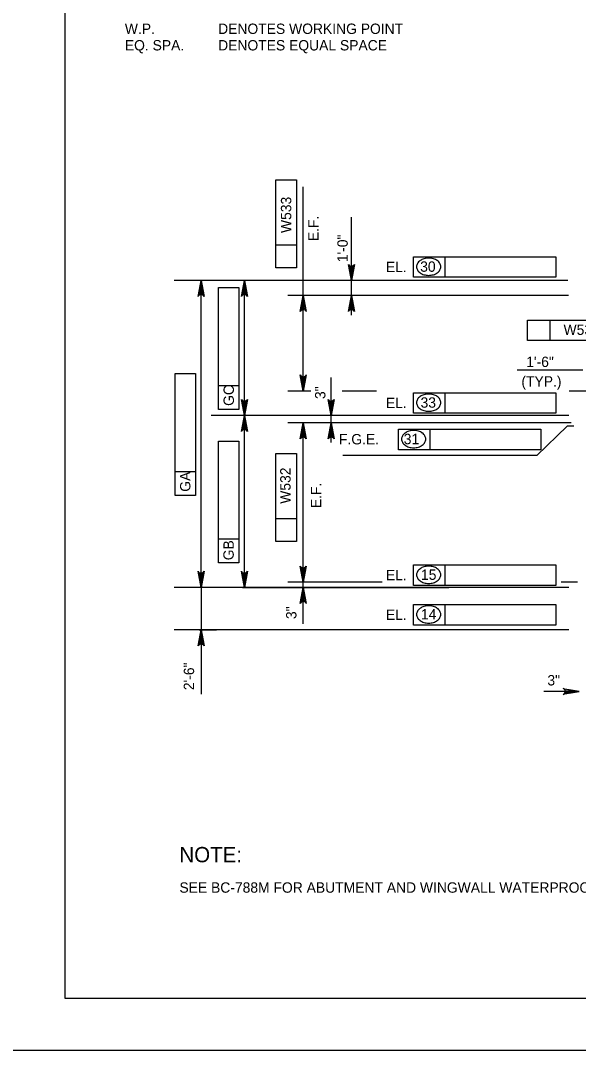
# Model space of a CAD drawing. Extents: x 638340 to 640242, y 295465 to 298435.
# Drawn here: x 639303.6 to 639464.9, y 297841.5 to 298139.3 of the extents above; entities that cross this region are included whole.
import ezdxf

# ---------------------------------------------------------------- set-up
doc = ezdxf.new("R2010")
doc.units = 0
for name, color, linetype in [('2', 7, 'Continuous'), ('4', 7, 'Continuous'), ('Level 3', 7, 'Continuous'), ('Level 4', 7, 'Continuous'), ('PLT-BNDY', 7, 'Continuous')]:
    doc.layers.add(name, color=color, linetype=linetype)

msp = doc.modelspace()

# ---------------------------------------------------------------- linework, layer by layer
at = {"layer": '2'}
for p, q in [((639316.46, 297856.46), (639316.46, 298420.46)), ((640102.46, 297856.46), (639316.46, 297856.46))]:
    msp.add_line(p, q, dxfattribs=at)
at = {"layer": 'Level 3'}
for p, q in [((639466.19, 298038.15), (639447.21, 298038.15)), ((639463.59, 298022.02), (639461.64, 298022.02))]:
    msp.add_line(p, q, dxfattribs=at)
at = {"layer": 'Level 4'}
for p, q in [((639377.42, 298067.77), (639377.42, 298093.26)), ((639377.42, 298093.26), (639383.32, 298093.26)), ((639383.32, 298093.26), (639383.32, 298067.77)), ((639385.3, 298035.1), (639385.3, 298091.24)), ((639399.23, 298054.11), (639399.23, 298082.41)), ((639383.32, 298074.35), (639377.42, 298074.35)), ((639417.21, 298070.94), (639458.34, 298070.94)), ((639417.21, 298065.04), (639417.21, 298070.94)), ((639426.36, 298065.04), (639426.36, 298070.94)), ((639458.34, 298070.94), (639458.34, 298065.04)), ((639383.32, 298067.77), (639377.42, 298067.77)), ((639461.86, 298064.14), (639347.97, 298064.14)), ((639363.31, 298064.14), (639351.37, 298064.14)), ((639380.68, 298064.14), (639363.89, 298064.14)), ((639427.63, 298064.14), (639391.86, 298064.14)), ((639458.34, 298065.04), (639417.21, 298065.04)), ((639355.79, 297978.3), (639355.79, 298061.19)), ((639360.79, 298026.83), (639360.79, 298062.07)), ((639360.79, 298062.07), (639366.69, 298062.07)), ((639366.69, 298062.07), (639366.69, 298026.83)), ((639368.31, 298028.04), (639368.31, 298061.19)), ((639461.97, 298059.78), (639380.88, 298059.78)), ((639450.16, 298052.66), (639475.65, 298052.66)), ((639450.16, 298046.76), (639450.16, 298052.66)), ((639456.74, 298046.76), (639456.74, 298052.66)), ((639475.65, 298046.76), (639450.16, 298046.76)), ((639348.27, 298001.97), (639348.27, 298037.2)), ((639348.27, 298037.2), (639354.16, 298037.2)), ((639354.16, 298037.2), (639354.16, 298001.97)), ((639393.36, 298017.27), (639393.36, 298036.04)), ((639366.69, 298033.67), (639360.79, 298033.67)), ((639387.51, 298032.15), (639380.88, 298032.15)), ((639406.53, 298032.15), (639396.53, 298032.15)), ((639417.21, 298031.63), (639458.34, 298031.63)), ((639417.21, 298025.74), (639417.21, 298031.63)), ((639426.36, 298025.74), (639426.36, 298031.63)), ((639458.34, 298031.63), (639458.34, 298025.74)), ((639478.24, 298032.15), (639462.24, 298032.15)), ((639462.14, 298025.09), (639358.72, 298025.09)), ((639366.69, 298026.83), (639360.79, 298026.83)), ((639434.02, 298025.09), (639363.89, 298025.09)), ((639427.63, 298025.09), (639363.89, 298025.09)), ((639458.34, 298025.74), (639417.21, 298025.74)), ((639368.31, 297978.3), (639368.31, 298022.14)), ((639462.75, 298022.94), (639380.88, 298022.94)), ((639461.64, 298022.02), (639452.82, 298013.52)), ((639385.3, 297975.36), (639385.3, 298019.99)), ((639412.87, 298021.08), (639454, 298021.08)), ((639412.87, 298015.19), (639412.87, 298021.08)), ((639422.03, 298015.19), (639422.03, 298021.08)), ((639454, 298021.08), (639454, 298015.19)), ((639360.79, 297982.44), (639360.79, 298017.68)), ((639360.79, 298017.68), (639366.69, 298017.68)), ((639366.69, 298017.68), (639366.69, 297982.44)), ((639454, 298015.19), (639412.87, 298015.19)), ((639377.42, 297988.6), (639377.42, 298014.09)), ((639377.42, 298014.09), (639383.32, 298014.09)), ((639383.32, 298014.09), (639383.32, 297988.6)), ((639452.82, 298013.52), (639396.79, 298013.52)), ((639354.16, 298008.8), (639348.27, 298008.8)), ((639354.16, 298001.97), (639348.27, 298001.97)), ((639383.32, 297995.18), (639377.42, 297995.18)), ((639366.69, 297989.28), (639360.79, 297989.28)), ((639383.32, 297988.6), (639377.42, 297988.6)), ((639366.69, 297982.44), (639360.79, 297982.44)), ((639417.21, 297981.84), (639458.34, 297981.84)), ((639417.21, 297975.94), (639417.21, 297981.84)), ((639426.36, 297975.94), (639426.36, 297981.84)), ((639458.34, 297981.84), (639458.34, 297975.94)), ((639408.14, 297976.89), (639380.88, 297976.89)), ((639464.62, 297976.89), (639459.85, 297976.89)), ((639462.14, 297975.36), (639347.97, 297975.36)), ((639363.31, 297975.36), (639351.37, 297975.36)), ((639355.79, 297975.36), (639355.79, 297963.08)), ((639434.02, 297975.36), (639363.89, 297975.36)), ((639367.71, 297975.36), (639427.45, 297975.36)), ((639458.34, 297975.94), (639417.21, 297975.94)), ((639385.3, 297964.81), (639385.3, 297972.41)), ((639417.21, 297970.37), (639458.34, 297970.37)), ((639417.21, 297964.48), (639417.21, 297970.37)), ((639426.36, 297964.48), (639426.36, 297970.37)), ((639458.34, 297970.37), (639458.34, 297964.48)), ((639388.75, 297963.08), (639347.97, 297963.08)), ((639355.19, 297963.08), (639360.21, 297963.08)), ((639462.14, 297963.08), (639388.75, 297963.08)), ((639458.34, 297964.48), (639417.21, 297964.48)), ((639355.79, 297960.13), (639355.79, 297944.5)), ((639459.23, 297945.27), (639454.86, 297945.27)), ((639462.18, 297945.27), (639459.23, 297945.27))]:
    msp.add_line(p, q, dxfattribs=at)
for points in [[(639399.23, 298064.14), (639398.36, 298068.79), (639398.61, 298068.43), (639398.92, 298068.25), (639399.23, 298068.19), (639399.55, 298068.25), (639399.86, 298068.43), (639400.1, 298068.79), (639399.23, 298064.14), (639399.86, 298068.43), (639399.55, 298068.25), (639399.23, 298064.14), (639399.23, 298068.19), (639398.92, 298068.25), (639399.23, 298064.14), (639398.61, 298068.43)], [(639355.79, 298064.14), (639356.66, 298059.49), (639356.41, 298059.84), (639356.1, 298060.03), (639355.79, 298060.08), (639355.48, 298060.03), (639355.16, 298059.84), (639354.92, 298059.49), (639355.79, 298064.14), (639355.16, 298059.84), (639355.48, 298060.03), (639355.79, 298064.14), (639355.79, 298060.08), (639356.1, 298060.03), (639355.79, 298064.14), (639356.41, 298059.84)], [(639368.31, 298064.14), (639369.18, 298059.49), (639368.93, 298059.84), (639368.62, 298060.03), (639368.31, 298060.08), (639368, 298060.03), (639367.69, 298059.84), (639367.44, 298059.49), (639368.31, 298064.14), (639367.69, 298059.84), (639368, 298060.03), (639368.31, 298064.14), (639368.31, 298060.08), (639368.62, 298060.03), (639368.31, 298064.14), (639368.93, 298059.84)], [(639385.3, 298059.78), (639386.17, 298055.13), (639385.92, 298055.49), (639385.61, 298055.67), (639385.3, 298055.72), (639384.99, 298055.67), (639384.67, 298055.49), (639384.43, 298055.13), (639385.3, 298059.78), (639384.67, 298055.49), (639384.99, 298055.67), (639385.3, 298059.78), (639385.3, 298055.72), (639385.61, 298055.67), (639385.3, 298059.78), (639385.92, 298055.49)], [(639399.23, 298059.78), (639400.1, 298055.13), (639399.86, 298055.49), (639399.55, 298055.67), (639399.23, 298055.72), (639398.92, 298055.67), (639398.61, 298055.49), (639398.36, 298055.13), (639399.23, 298059.78), (639398.61, 298055.49), (639398.92, 298055.67), (639399.23, 298059.78), (639399.23, 298055.72), (639399.55, 298055.67), (639399.23, 298059.78), (639399.86, 298055.49)], [(639385.3, 298032.15), (639384.43, 298036.8), (639384.67, 298036.44), (639384.99, 298036.26), (639385.3, 298036.2), (639385.61, 298036.26), (639385.92, 298036.44), (639386.17, 298036.8), (639385.3, 298032.15), (639385.92, 298036.44), (639385.61, 298036.26), (639385.3, 298032.15), (639385.3, 298036.2), (639384.99, 298036.26), (639385.3, 298032.15), (639384.67, 298036.44)], [(639368.31, 298025.09), (639367.44, 298029.74), (639367.69, 298029.38), (639368, 298029.2), (639368.31, 298029.14), (639368.62, 298029.2), (639368.93, 298029.38), (639369.18, 298029.74), (639368.31, 298025.09), (639368.93, 298029.38), (639368.62, 298029.2), (639368.31, 298025.09), (639368.31, 298029.14), (639368, 298029.2), (639368.31, 298025.09), (639367.69, 298029.38)], [(639393.36, 298025.09), (639392.48, 298029.74), (639392.73, 298029.38), (639393.04, 298029.2), (639393.36, 298029.14), (639393.67, 298029.2), (639393.98, 298029.38), (639394.23, 298029.74), (639393.36, 298025.09), (639393.98, 298029.38), (639393.67, 298029.2), (639393.36, 298025.09), (639393.36, 298029.14), (639393.04, 298029.2), (639393.36, 298025.09), (639392.73, 298029.38)], [(639368.31, 298025.09), (639369.18, 298020.44), (639368.93, 298020.8), (639368.62, 298020.98), (639368.31, 298021.03), (639368, 298020.98), (639367.69, 298020.8), (639367.44, 298020.44), (639368.31, 298025.09), (639367.69, 298020.8), (639368, 298020.98), (639368.31, 298025.09), (639368.31, 298021.03), (639368.62, 298020.98), (639368.31, 298025.09), (639368.93, 298020.8)], [(639385.3, 298022.94), (639386.17, 298018.29), (639385.92, 298018.65), (639385.61, 298018.83), (639385.3, 298018.88), (639384.99, 298018.83), (639384.67, 298018.65), (639384.43, 298018.29), (639385.3, 298022.94), (639384.67, 298018.65), (639384.99, 298018.83), (639385.3, 298022.94), (639385.3, 298018.88), (639385.61, 298018.83), (639385.3, 298022.94), (639385.92, 298018.65)], [(639393.36, 298022.94), (639394.23, 298018.29), (639393.98, 298018.65), (639393.67, 298018.83), (639393.36, 298018.88), (639393.04, 298018.83), (639392.73, 298018.65), (639392.48, 298018.29), (639393.36, 298022.94), (639392.73, 298018.65), (639393.04, 298018.83), (639393.36, 298022.94), (639393.36, 298018.88), (639393.67, 298018.83), (639393.36, 298022.94), (639393.98, 298018.65)], [(639355.79, 297975.36), (639354.92, 297980.01), (639355.16, 297979.65), (639355.48, 297979.46), (639355.79, 297979.41), (639356.1, 297979.46), (639356.41, 297979.65), (639356.66, 297980.01), (639355.79, 297975.36), (639356.41, 297979.65), (639356.1, 297979.46), (639355.79, 297975.36), (639355.79, 297979.41), (639355.48, 297979.46), (639355.79, 297975.36), (639355.16, 297979.65)], [(639368.31, 297975.36), (639367.44, 297980.01), (639367.69, 297979.65), (639368, 297979.46), (639368.31, 297979.41), (639368.62, 297979.46), (639368.93, 297979.65), (639369.18, 297980.01), (639368.31, 297975.36), (639368.93, 297979.65), (639368.62, 297979.46), (639368.31, 297975.36), (639368.31, 297979.41), (639368, 297979.46), (639368.31, 297975.36), (639367.69, 297979.65)], [(639385.3, 297976.89), (639384.43, 297981.54), (639384.67, 297981.19), (639384.99, 297981), (639385.3, 297980.95), (639385.61, 297981), (639385.92, 297981.19), (639386.17, 297981.54), (639385.3, 297976.89), (639385.92, 297981.19), (639385.61, 297981), (639385.3, 297976.89), (639385.3, 297980.95), (639384.99, 297981), (639385.3, 297976.89), (639384.67, 297981.19)], [(639385.3, 297975.36), (639386.17, 297970.7), (639385.92, 297971.06), (639385.61, 297971.25), (639385.3, 297971.3), (639384.99, 297971.25), (639384.67, 297971.06), (639384.43, 297970.7), (639385.3, 297975.36), (639384.67, 297971.06), (639384.99, 297971.25), (639385.3, 297975.36), (639385.3, 297971.3), (639385.61, 297971.25), (639385.3, 297975.36), (639385.92, 297971.06)], [(639355.79, 297963.08), (639356.66, 297958.43), (639356.41, 297958.78), (639356.1, 297958.97), (639355.79, 297959.02), (639355.48, 297958.97), (639355.16, 297958.78), (639354.92, 297958.43), (639355.79, 297963.08), (639355.16, 297958.78), (639355.48, 297958.97), (639355.79, 297963.08), (639355.79, 297959.02), (639356.1, 297958.97), (639355.79, 297963.08), (639356.41, 297958.78)], [(639465.13, 297945.27), (639460.48, 297944.4), (639460.83, 297944.64), (639461.02, 297944.96), (639461.07, 297945.27), (639461.02, 297945.58), (639460.83, 297945.89), (639460.48, 297946.14), (639465.13, 297945.27), (639460.83, 297945.89), (639461.02, 297945.58), (639465.13, 297945.27), (639461.07, 297945.27), (639461.02, 297944.96), (639465.13, 297945.27), (639460.83, 297944.64)]]:
    msp.add_lwpolyline(points, dxfattribs=at)
for points in [[(639398.74, 298067.08), (639399.72, 298067.08), (639399.23, 298064.14)], [(639355.29, 298061.19), (639356.28, 298061.19), (639355.79, 298064.14)], [(639367.82, 298061.19), (639368.8, 298061.19), (639368.31, 298064.14)], [(639384.81, 298056.83), (639385.79, 298056.83), (639385.3, 298059.78)], [(639398.74, 298056.83), (639399.72, 298056.83), (639399.23, 298059.78)], [(639384.81, 298035.1), (639385.79, 298035.1), (639385.3, 298032.15)], [(639367.82, 298028.04), (639368.8, 298028.04), (639368.31, 298025.09)], [(639392.86, 298028.04), (639393.85, 298028.04), (639393.36, 298025.09)], [(639367.82, 298022.14), (639368.8, 298022.14), (639368.31, 298025.09)], [(639384.81, 298019.99), (639385.79, 298019.99), (639385.3, 298022.94)], [(639392.86, 298019.99), (639393.85, 298019.99), (639393.36, 298022.94)], [(639384.81, 297979.84), (639385.79, 297979.84), (639385.3, 297976.89)], [(639355.29, 297978.3), (639356.28, 297978.3), (639355.79, 297975.36)], [(639367.82, 297978.3), (639368.8, 297978.3), (639368.31, 297975.36)], [(639384.81, 297972.41), (639385.79, 297972.41), (639385.3, 297975.36)], [(639355.29, 297960.13), (639356.28, 297960.13), (639355.79, 297963.08)], [(639462.18, 297945.76), (639462.18, 297944.77), (639465.13, 297945.27)]]:
    msp.add_lwpolyline(points, close=True, dxfattribs=at)
for centre, radius, start, end in [((639419.9, 298068.1), 1.82, 149.9767, 180), ((639420.71, 298067.63), 2.75, 125.6316, 149.9767), ((639421.23, 298066.9), 3.65, 106.5358, 125.6316), ((639421.58, 298065.74), 4.86, 90, 106.5358), ((639421.58, 298065.74), 4.86, 73.4642, 90), ((639421.92, 298066.9), 3.65, 54.3684, 73.4642), ((639422.45, 298067.63), 2.75, 30.0233, 54.3684), ((639423.25, 298068.1), 1.82, 0, 30.0233), ((639419.9, 298068.1), 1.82, 180, 210.0233), ((639420.71, 298068.56), 2.75, 210.0233, 234.3684), ((639421.23, 298069.3), 3.65, 234.3684, 253.4642), ((639421.92, 298069.3), 3.65, 286.5358, 305.6316), ((639422.45, 298068.56), 2.75, 305.6316, 329.9767), ((639423.25, 298068.1), 1.82, 329.9767, 0), ((639421.58, 298070.46), 4.86, 253.4642, 270), ((639421.58, 298070.46), 4.86, 270, 286.5358), ((639420.71, 298028.33), 2.75, 125.6316, 149.9767), ((639421.23, 298027.59), 3.65, 106.5358, 125.6316), ((639421.58, 298026.43), 4.86, 90, 106.5358), ((639421.58, 298026.43), 4.86, 73.4642, 90), ((639421.92, 298027.59), 3.65, 54.3684, 73.4642), ((639422.45, 298028.33), 2.75, 30.0233, 54.3684), ((639419.9, 298028.79), 1.82, 149.9767, 180), ((639419.9, 298028.79), 1.82, 180, 210.0233), ((639420.71, 298029.25), 2.75, 210.0233, 234.3684), ((639422.45, 298029.25), 2.75, 305.6316, 329.9767), ((639423.25, 298028.79), 1.82, 0, 30.0233), ((639423.25, 298028.79), 1.82, 329.9767, 0), ((639421.23, 298029.99), 3.65, 234.3684, 253.4642), ((639421.58, 298031.15), 4.86, 253.4642, 270), ((639421.58, 298031.15), 4.86, 270, 286.5358), ((639421.92, 298029.99), 3.65, 286.5358, 305.6316), ((639415.57, 298018.24), 1.82, 149.9767, 180), ((639415.57, 298018.24), 1.82, 180, 210.0233), ((639416.37, 298017.78), 2.75, 125.6316, 149.9767), ((639416.9, 298017.04), 3.65, 106.5358, 125.6316), ((639417.24, 298015.89), 4.86, 90, 106.5358), ((639417.24, 298015.89), 4.86, 73.4642, 90), ((639417.59, 298017.04), 3.65, 54.3684, 73.4642), ((639418.11, 298017.78), 2.75, 30.0233, 54.3684), ((639418.91, 298018.24), 1.82, 0, 30.0233), ((639418.91, 298018.24), 1.82, 329.9767, 0), ((639416.37, 298018.71), 2.75, 210.0233, 234.3684), ((639416.9, 298019.44), 3.65, 234.3684, 253.4642), ((639417.24, 298020.6), 4.86, 253.4642, 270), ((639417.24, 298020.6), 4.86, 270, 286.5358), ((639417.59, 298019.44), 3.65, 286.5358, 305.6316), ((639418.11, 298018.71), 2.75, 305.6316, 329.9767), ((639419.9, 297979), 1.82, 149.9767, 180), ((639420.71, 297978.53), 2.75, 125.6316, 149.9767), ((639421.23, 297977.8), 3.65, 106.5358, 125.6316), ((639421.58, 297976.64), 4.86, 90, 106.5358), ((639421.58, 297976.64), 4.86, 73.4642, 90), ((639421.92, 297977.8), 3.65, 54.3684, 73.4642), ((639422.45, 297978.53), 2.75, 30.0233, 54.3684), ((639423.25, 297979), 1.82, 0, 30.0233), ((639419.9, 297979), 1.82, 180, 210.0233), ((639420.71, 297979.46), 2.75, 210.0233, 234.3684), ((639421.23, 297980.2), 3.65, 234.3684, 253.4642), ((639421.58, 297981.35), 4.86, 253.4642, 270), ((639421.58, 297981.35), 4.86, 270, 286.5358), ((639421.92, 297980.2), 3.65, 286.5358, 305.6316), ((639422.45, 297979.46), 2.75, 305.6316, 329.9767), ((639423.25, 297979), 1.82, 329.9767, 0), ((639419.9, 297967.53), 1.82, 149.9767, 180), ((639419.9, 297967.53), 1.82, 180, 210.0233), ((639420.71, 297967.07), 2.75, 125.6316, 149.9767), ((639421.23, 297966.34), 3.65, 106.5358, 125.6316), ((639421.58, 297965.18), 4.86, 90, 106.5358), ((639421.58, 297965.18), 4.86, 73.4642, 90), ((639421.92, 297966.34), 3.65, 54.3684, 73.4642), ((639422.45, 297967.07), 2.75, 30.0233, 54.3684), ((639423.25, 297967.53), 1.82, 0, 30.0233), ((639423.25, 297967.53), 1.82, 329.9767, 0), ((639420.71, 297968), 2.75, 210.0233, 234.3684), ((639421.23, 297968.73), 3.65, 234.3684, 253.4642), ((639421.58, 297969.89), 4.86, 253.4642, 270), ((639421.58, 297969.89), 4.86, 270, 286.5358), ((639421.92, 297968.73), 3.65, 286.5358, 305.6316), ((639422.45, 297968), 2.75, 305.6316, 329.9767)]:
    msp.add_arc(centre, radius, start, end, dxfattribs=at)
at = {"layer": 'PLT-BNDY'}
msp.add_lwpolyline([(639276.46, 298435.46), (640117.46, 298435.46), (640117.46, 297841.46), (639276.46, 297841.46)], close=True, dxfattribs=at)

# ---------------------------------------------------------------- texts
at = {"layer": '2'}
msp.add_text('SEE BC-788M FOR ABUTMENT AND WINGWALL WATERPROOFING DETAIL.', height=3.0001, dxfattribs=at).set_placement((639349.5, 297887.06))
at = {"layer": '4'}
msp.add_text('NOTE:', height=4.429, dxfattribs=at).set_placement((639349.5, 297895.86))
at = {"layer": 'Level 3'}
for s, p in [('1\'-6"', (639449.78, 298039.1)), ('(TYP.)', (639448.39, 298033.45))]:
    msp.add_text(s, height=3, dxfattribs=at).set_placement(p)
at = {"layer": 'Level 4'}
for s, height, p in [('W.P.', 3, (639333.72, 298135.42)), ('DENOTES WORKING POINT', 3.0001, (639360.7, 298135.42)), ('EQ. SPA.', 3, (639333.72, 298130.65)), ('DENOTES EQUAL SPACE', 3.0001, (639360.7, 298130.65)), ('EL.', 3, (639409.2, 298066.53)), ('30', 3, (639419.12, 298066.64)), ('W534', 3, (639460.58, 298048.39)), ('EL.', 3, (639409.2, 298027.22)), ('33', 3, (639419.23, 298027.33)), ('F.G.E.', 3, (639395.64, 298016.72)), ('31', 3, (639414.37, 298016.78)), ('EL.', 3, (639409.2, 297977.43)), ('15', 3, (639419.36, 297977.54)), ('EL.', 3, (639409.2, 297965.96)), ('14', 3, (639419.34, 297966.08)), ('3"', 3, (639455.91, 297947))]:
    msp.add_text(s, height=height, dxfattribs=at).set_placement(p)
for s, p in [('W533', (639381.84, 298077.85)), ('E.F.', (639389.74, 298075.5)), ('1\'-0"', (639398.17, 298069.41)), ('GC', (639365.26, 298027.85)), ('3"', (639391.72, 298029.84)), ('W532', (639381.64, 297999.55)), ('GA', (639352.68, 298003.02)), ('E.F.', (639390.51, 297998.3)), ('GB', (639365.21, 297983.21)), ('3"', (639383.35, 297966.21)), ('2\'-6"', (639353.75, 297945.64))]:
    msp.add_text(s, height=3, rotation=90, dxfattribs=at).set_placement(p)

doc.saveas('drawing.dxf')
